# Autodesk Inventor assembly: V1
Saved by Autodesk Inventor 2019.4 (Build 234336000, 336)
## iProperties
Created: 2020-01
Part Number: V1
Document SubType Name: Assembly
Designer: Administrator
Title: V1 v9
Author: Administrator
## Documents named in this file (3)
- c:\worker\convert-fusion-r01\tmp\job-1\61\output\files\aee60a31-d91c-4752-9293-a14cfbf1decc\b67b4387-235d-4aeb-86a2-01a8e20c7cb8.iam
- c:\worker\convert-fusion-r01\tmp\job-1\61\output\files\aee60a31-d91c-4752-9293-a14cfbf1decc\untitled v4.iam
- c:\worker\convert-fusion-r01\tmp\job-1\61\output\files\aee60a31-d91c-4752-9293-a14cfbf1decc\V1 v9.ipt
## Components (2 placed, 2 different names)
1. untitled v4:1 [sub-assembly]
2. V1 v9
